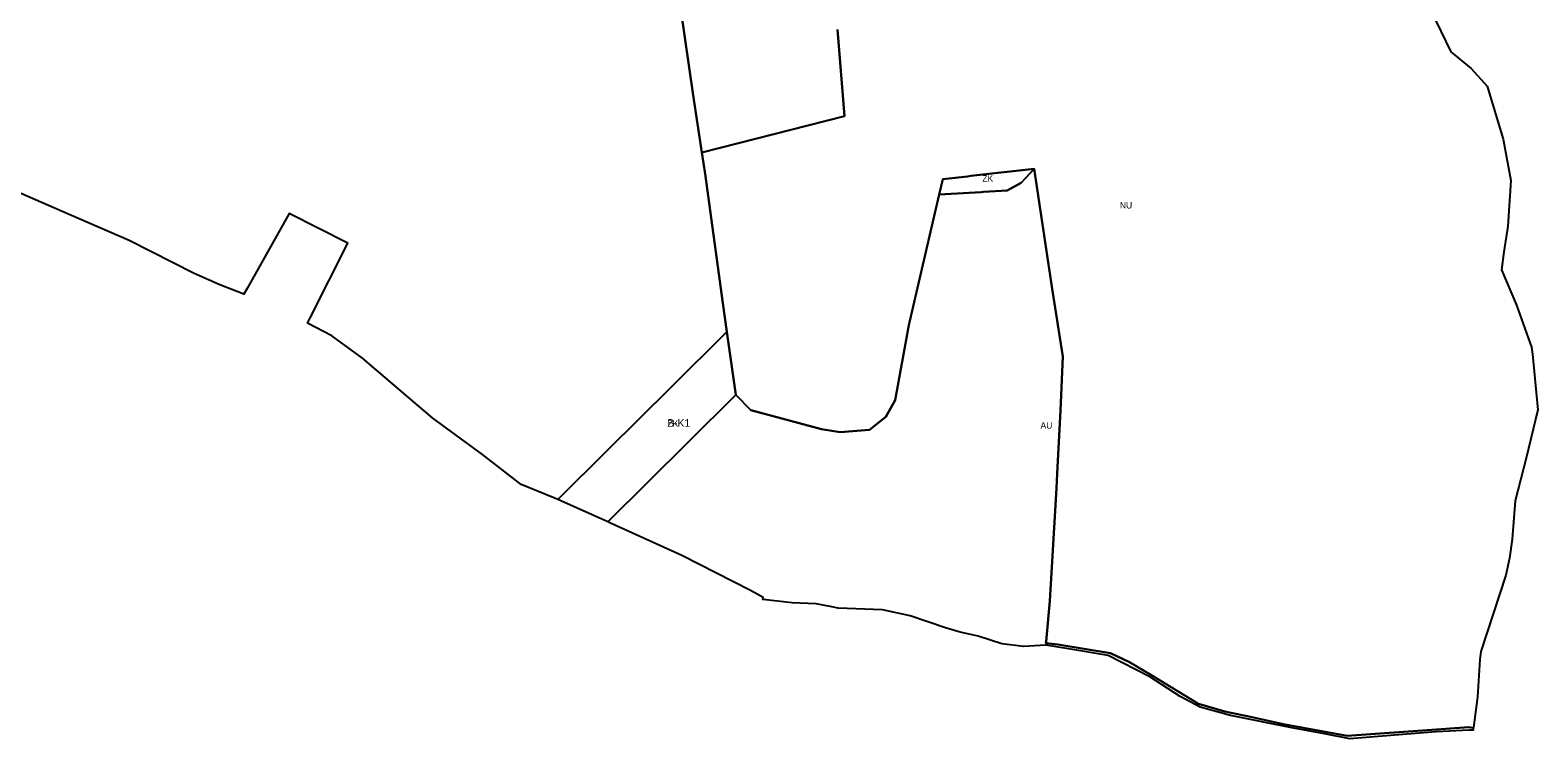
# Model space of a CAD drawing. Extents: x -532067 to -529270, y -1180561 to -1176456.
# Drawn here: x -530711 to -529531, y -1180561 to -1180006 of the extents above; entities that cross this region are included whole.
import ezdxf

# ---------------------------------------------------------------- set-up
doc = ezdxf.new("R2010")
doc.units = 0
for name, color, linetype in [('90710013', 7, 'Continuous'), ('90710023', 7, 'Continuous'), ('90730013', 7, 'Continuous'), ('90750013', 7, 'Continuous'), ('90770013', 7, 'Continuous'), ('ID_navrh', 7, 'Continuous')]:
    doc.layers.add(name, color=color, linetype=linetype)

msp = doc.modelspace()

# ---------------------------------------------------------------- linework, layer by layer
at = {"layer": '90710013'}
msp.add_lwpolyline([(-529966.6423, -1180133.14345), (-529999.2953, -1180134.98045), (-529996.5353, -1180123.13245), (-529977.1493, -1180121.02645), (-529974.7203, -1180120.55445), (-529925.1553, -1180115.06945), (-529935.2823, -1180125.95745), (-529946.2373, -1180131.99545), (-529964.7143, -1180133.03545)], close=True, dxfattribs=at)
at = {"layer": '90710023'}
msp.add_lwpolyline([(-530158.5353, -1180291.94345), (-530195.8903, -1180329.01545), (-530258.7883, -1180391.43945), (-530297.9263, -1180373.92745), (-530258.6793, -1180334.97645), (-530209.7653, -1180286.43145), (-530165.5053, -1180242.50645)], close=True, dxfattribs=at)
at = {"layer": '90730013'}
msp.add_lwpolyline([(-529610.7653, -1179999.24045), (-529598.9323, -1180023.30345), (-529582.9963, -1180036.56345), (-529570.5013, -1180050.18745), (-529558.0573, -1180091.81745), (-529552.1033, -1180124.02445), (-529554.4423, -1180159.85745), (-529557.4193, -1180179.90645), (-529559.3433, -1180194.16845), (-529547.5773, -1180221.76545), (-529535.8103, -1180254.74245), (-529535.0893, -1180260.11145), (-529530.8873, -1180303.59345), (-529540.1513, -1180341.45445), (-529548.7033, -1180374.92745), (-529551.0503, -1180404.86745), (-529553.0633, -1180419.83745), (-529555.8713, -1180433.00145), (-529575.5323, -1180492.87245), (-529576.2223, -1180499.17045), (-529578.0823, -1180528.26345), (-529581.3663, -1180552.30645), (-529581.4133, -1180552.68645), (-529584.7973, -1180552.18545), (-529621.2543, -1180554.62345), (-529654.5663, -1180557.20545), (-529680.1093, -1180558.87645), (-529729.8773, -1180549.89945), (-529754.5253, -1180544.38745), (-529775.9353, -1180539.98745), (-529796.4593, -1180533.76945), (-529833.2373, -1180511.38445), (-529850.5923, -1180501.15945), (-529865.2333, -1180494.21345), (-529906.5923, -1180487.50745), (-529915.9223, -1180486.25045), (-529915.8003, -1180485.15545), (-529915.5293, -1180482.12345), (-529912.7673, -1180453.11945), (-529911.1793, -1180426.75845), (-529907.7113, -1180365.01045), (-529907.1193, -1180353.49345), (-529904.5833, -1180304.12645), (-529902.6953, -1180262.04745), (-529910.8683, -1180209.02745), (-529913.3373, -1180193.27945), (-529925.1553, -1180115.06945), (-529974.7203, -1180120.55445), (-529977.1493, -1180121.02645), (-529996.5353, -1180123.13245), (-529999.2953, -1180134.98045), (-530023.1713, -1180237.48045), (-530033.7833, -1180296.19445), (-530041.0783, -1180309.13045), (-530053.8703, -1180319.33745), (-530076.8933, -1180321.07245), (-530091.4843, -1180318.75045), (-530146.8633, -1180303.82345), (-530158.5353, -1180291.94345), (-530165.5053, -1180242.50645), (-530168.6483, -1180220.21745), (-530182.5403, -1180119.03445), (-530185.1123, -1180102.30345), (-530073.5353, -1180073.74245), (-530079.0333, -1180006.03545)], dxfattribs=at)
at = {"layer": '90750013'}
msp.add_lwpolyline([(-530205.0143, -1179966.75845), (-530192.0373, -1180057.25345), (-530185.1123, -1180102.30345), (-530182.5403, -1180119.03445), (-530168.6483, -1180220.21745), (-530165.5053, -1180242.50645), (-530209.7653, -1180286.43145), (-530258.6793, -1180334.97645), (-530297.9263, -1180373.92745), (-530300.9453, -1180372.57645), (-530326.4543, -1180362.02045), (-530356.7463, -1180338.67045), (-530395.6473, -1180310.20145), (-530415.0983, -1180293.88845), (-530450.8103, -1180263.18045), (-530474.7983, -1180245.76745), (-530493.8363, -1180235.70845), (-530491.7793, -1180231.65645), (-530462.1243, -1180173.23245), (-530508.0783, -1180149.90845), (-530540.6773, -1180208.10545), (-530543.5213, -1180213.18245), (-530562.4933, -1180205.75145), (-530582.4383, -1180196.85845), (-530633.4093, -1180171.13445), (-530680.2893, -1180150.82445), (-530722.8103, -1180132.24845)], dxfattribs=at)
msp.add_lwpolyline([(-529904.5833, -1180304.12645), (-529907.1193, -1180353.49345), (-529907.7113, -1180365.01045), (-529911.1793, -1180426.75845), (-529912.7673, -1180453.11945), (-529915.5293, -1180482.12345), (-529915.8003, -1180485.15545), (-529915.9223, -1180486.25045), (-529906.5923, -1180487.50745), (-529865.2333, -1180494.21345), (-529850.5923, -1180501.15945), (-529833.2373, -1180511.38445), (-529796.4593, -1180533.76945), (-529775.9353, -1180539.98745), (-529754.5253, -1180544.38745), (-529729.8773, -1180549.89945), (-529680.1093, -1180558.87645), (-529654.5663, -1180557.20545), (-529621.2543, -1180554.62345), (-529584.7973, -1180552.18545), (-529581.4133, -1180552.68645), (-529581.6293, -1180554.42945), (-529584.6303, -1180554.39145), (-529610.3833, -1180555.73045), (-529633.4643, -1180557.64445), (-529678.1023, -1180561.28045), (-529697.7713, -1180557.46945), (-529723.4733, -1180552.59845), (-529771.4523, -1180543.00145), (-529795.1553, -1180536.41245), (-529810.8833, -1180528.12745), (-529834.4333, -1180512.74345), (-529867.1573, -1180496.12445), (-529898.1013, -1180490.90445), (-529915.8543, -1180487.95345), (-529933.3033, -1180489.07045), (-529950.2583, -1180486.90045), (-529968.9873, -1180480.86145), (-529983.0333, -1180477.67345), (-529994.5723, -1180474.31845), (-530021.9963, -1180465.09245), (-530043.7343, -1180460.39545), (-530078.3493, -1180458.88645), (-530083.4813, -1180457.89445), (-530095.6203, -1180455.54445), (-530114.5753, -1180454.79645), (-530137.3633, -1180452.12545), (-530137.2573, -1180450.52345), (-530141.8663, -1180447.95645), (-530147.0563, -1180445.06645), (-530200.8223, -1180417.82345), (-530256.6233, -1180392.40845), (-530258.7883, -1180391.43945), (-530195.8903, -1180329.01545), (-530158.5353, -1180291.94345), (-530146.8633, -1180303.82345), (-530091.4843, -1180318.75045), (-530076.8933, -1180321.07245), (-530053.8703, -1180319.33745), (-530041.0783, -1180309.13045), (-530033.7833, -1180296.19445), (-530023.1713, -1180237.48045), (-529999.2953, -1180134.98045), (-529966.6423, -1180133.14345), (-529964.7143, -1180133.03545), (-529946.2373, -1180131.99545), (-529935.2823, -1180125.95745), (-529925.1553, -1180115.06945), (-529913.3373, -1180193.27945), (-529910.8683, -1180209.02745), (-529902.6953, -1180262.04745)], close=True, dxfattribs=at)
at = {"layer": '90770013'}
msp.add_lwpolyline([(-530079.0333, -1180006.03545), (-530073.5353, -1180073.74245), (-530185.1123, -1180102.30345), (-530192.0373, -1180057.25345), (-530205.0143, -1179966.75845)], dxfattribs=at)

# ---------------------------------------------------------------- texts
at = {"layer": '90710013'}
msp.add_text('ZK', height=5, rotation=0.00000006, dxfattribs=at).set_placement((-529965.69557, -1180125.02495))
at = {"layer": '90710023'}
msp.add_text('ZK', height=5, rotation=359.99999995, dxfattribs=at).set_placement((-530212.14741, -1180316.97295))
at = {"layer": '90730013'}
msp.add_text('NU', height=5, rotation=0.00000002, dxfattribs=at).set_placement((-529857.9998, -1180146.0489))
at = {"layer": '90750013'}
msp.add_text('AU', height=5, rotation=0.00000006, dxfattribs=at).set_placement((-529920.1008, -1180318.37238))
at = {"layer": 'ID_navrh'}
msp.add_text('B-K1', height=6, rotation=359.99999999, dxfattribs=at).set_placement((-530212.14741, -1180316.97295))

doc.saveas('drawing.dxf')
